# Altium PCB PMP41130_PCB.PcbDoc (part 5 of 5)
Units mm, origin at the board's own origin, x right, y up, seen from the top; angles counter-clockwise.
Board outline 74.13 x 200.91 mm, 6 copper layers (Top Layer, Layer 1, Inside Layer 1, Inside Layer 2, Layer 2, Bottom Layer), stack 2.208 mm thick; 356 components, 162 nets, 889 pads, 1511 vias.
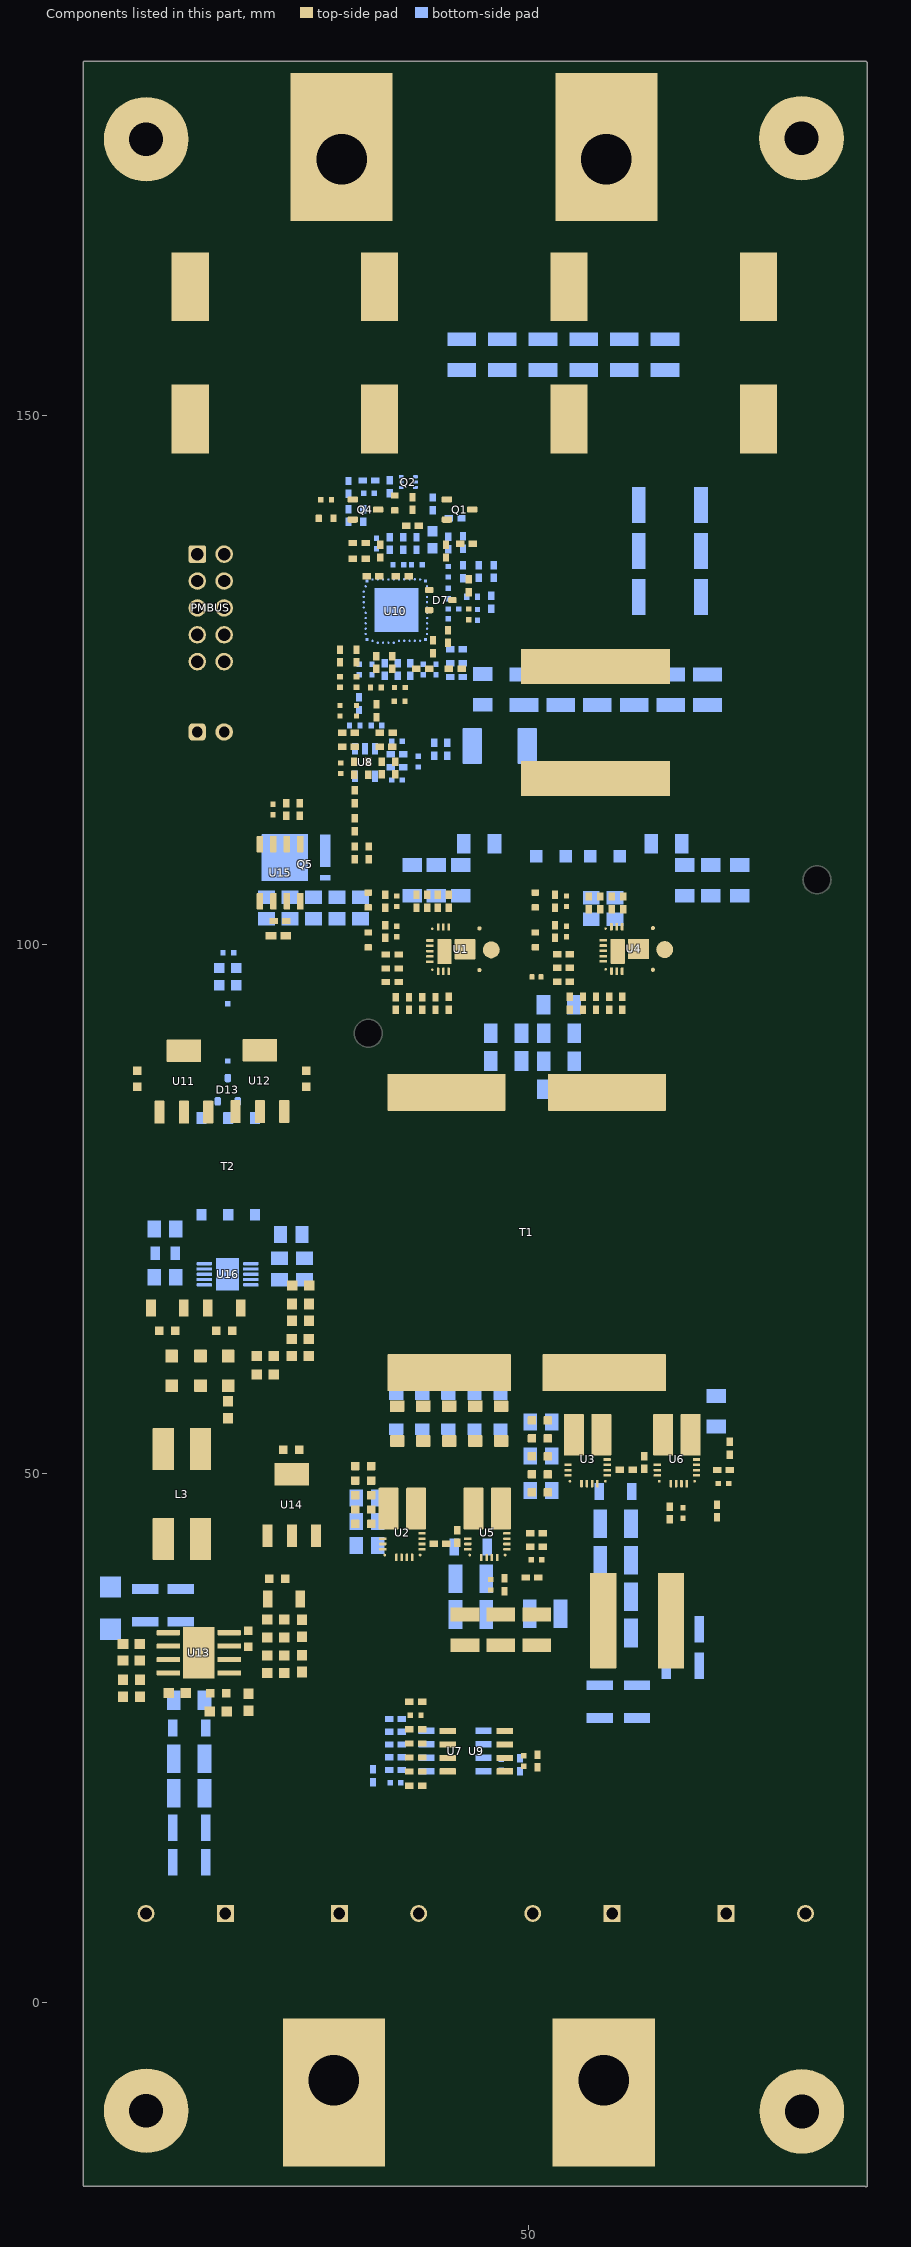
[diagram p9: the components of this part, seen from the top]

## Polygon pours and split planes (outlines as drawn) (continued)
SR_Source on Layer 2 "LAYER_2_SR_SOURCE_P201" (solid, remove dead copper, pour order 201): 43.648,112.63 46.238,115.219 46.238,120.747 38.988,120.747 38.988,114.483 36.03,114.483 36.03,112.125 38.988,109.168 38.988,98.9 39.846,98.042 63.538,98.042 64.269,98.773 64.269,101.19 43.648,101.19
SW3 on Layer 2 "LAYER_2_SW3_P186" (solid, remove dead copper, pour order 186): 59.882,95.876 59.882,90.943 59.154,90.215 55.037,90.215 55.037,84.24 63.665,84.24 63.665,95.876
SW4 on Layer 2 "LAYER_2_SW4_P183" (solid, remove dead copper, pour order 183): 43.459,95.876 43.459,91.061 43.026,90.628 38.212,90.628 37.348,89.764 37.348,84.266 47.828,84.266 47.828,95.876
GND on Layer 2 "LAYER_2_GND_P180" (solid, remove dead copper, pour order 180): 31.485,28.287 31.485,18.43 42.356,18.43 42.356,28.287
VOUT on Layer 2 "LAYER_2_VOUT_P153" (solid, remove dead copper, pour order 153): 62.459,127.394 52.655,127.394 52.655,146.557 51.72,147.492 8.046,147.492 8.046,154.902 68.533,154.902 68.533,144.5 68.268,144.234 62.459,144.234
AGND on Layer 2 "LAYER_2_AGND_P139" (solid, remove dead copper, pour order 139): 70.757,124.058 70.757,165.014 71.107,165.364 80.806,165.364 81.219,164.951 81.219,118.083 80.846,117.653 71.08,117.653 70.757,117.938
VIN_NEG on Layer 2 "LAYER_2_VIN_NEG_P103" (solid, remove dead copper, pour order 103): 32 vertices, not listed, extent 8.287,-15.551 81.124,10.431
VOUT on Layer 2 "LAYER_2_VOUT_P122" (solid, remove dead copper, pour order 122): 27.412,182.123 27.412,168.163 27.38,168.163 24.2,164.983 24.2,147.492 37.048,147.492 37.048,168.258 37.048,182.123
HS_Drain on Inside Layer 2 "INSIDE_LAYER_2_HS_DRAIN_P176" (solid, remove dead copper, pour order 176): 55.079,57.114 52.742,57.114 52.607,56.98 52.607,45.995 54.308,43.685 57.877,43.685 57.877,50.719 55.271,50.719 55.271,56.923
VIN_NEG on Inside Layer 2 "INSIDE_LAYER_2_VIN_NEG_P214" (solid, remove dead copper, pour order 214): 64.397,55.589 64.462,55.654 67.259,55.654 67.259,52.006 66.911,51.659 64.397,51.659
VIN_NEG on Inside Layer 2 "INSIDE_LAYER_2_VIN_NEG_P213" (solid, remove dead copper, pour order 213): 49.624,55.654 49.624,51.007 49.275,50.659 46.601,50.659 46.448,50.506 46.448,44.68 49.212,44.68 50.867,46.335 50.867,55.654
SR_Source on Inside Layer 2 "INSIDE_LAYER_2_SR_SOURCE_P210" (solid, remove dead copper, pour order 210): 38.988,100.766 38.988,98.9 39.624,98.264 45.889,98.264 63.761,98.264 64.269,98.773 64.269,100.766
SR_Source on Inside Layer 2 "INSIDE_LAYER_2_SR_SOURCE_P206" (solid, remove dead copper, pour order 206): 43.648,112.63 46.238,115.219 46.238,120.747 43.175,120.747 43.175,116.025 42.34,115.275 38.988,115.275 38.988,114.483 36.03,114.483 36.03,112.63
SR_Drain on Inside Layer 2 "INSIDE_LAYER_2_SR_DRAIN_P203" (solid, remove dead copper, pour order 203): 46.021,102.508 46.021,110.944 49.166,114.089 64.269,114.089 64.269,102.508 59.913,102.508 59.913,107.899 57.813,109.999 49.897,109.999 47.828,107.587 47.828,102.508
HS_Drain on Inside Layer 2 "INSIDE_LAYER_2_HS_DRAIN_P174" (solid, remove dead copper, pour order 174): 37.728,49.132 34.885,49.132 34.885,33.719 36.581,32.023 41.786,32.023 41.786,43.845 37.728,43.845
NetC1_2 on Inside Layer 2 "INSIDE_LAYER_2_NETC1_2_P195" (solid, remove dead copper, pour order 195): 36.889,57.736 36.889,62.427 48.348,62.427 48.348,57.736
SR_Drain on Inside Layer 2 "INSIDE_LAYER_2_SR_DRAIN_P134" (solid, remove dead copper, pour order 134): 47.828,108.659 34.377,108.659 34.377,110.969 46.07,110.969 47.828,112.728
SW3 on Inside Layer 2 "INSIDE_LAYER_2_SW3_P185" (solid, remove dead copper, pour order 185): 59.882,95.876 59.882,90.943 59.154,90.215 55.037,90.215 55.037,84.248 63.665,84.248 63.665,95.876
SW4 on Inside Layer 2 "INSIDE_LAYER_2_SW4_P182" (solid, remove dead copper, pour order 182): 43.459,95.876 43.459,91.061 43.026,90.628 39.022,90.628 37.895,89.501 37.895,84.269 47.828,84.269 47.828,95.876
HS_Drain on Inside Layer 2 "INSIDE_LAYER_2_HS_DRAIN_P175" (solid, remove dead copper, pour order 175): 54.31,46.175 57.877,46.175 57.877,32.023 39.512,32.023 39.512,35.013 54.31,35.013
VIN_NEG on Inside Layer 2 "INSIDE_LAYER_2_VIN_NEG_P173" (solid, remove dead copper, pour order 173): 16.09,26.584 8.682,26.584 8.682,1.622 8.936,1.367 15.646,1.367 16.09,1.811
SW2 on Inside Layer 2 "INSIDE_LAYER_2_SW2_P170" (solid, remove dead copper, pour order 170): 51.436,57.736 51.363,57.809 51.363,62.427 64.945,62.427 65.128,62.22 65.128,57.929 64.948,57.736 63.873,57.736 63.683,57.545 63.683,51.644 55.938,51.644 55.938,57.528 55.729,57.736
SW1 on Inside Layer 2 "INSIDE_LAYER_2_SW1_P169" (solid, remove dead copper, pour order 169): 36.996,51.931 36.889,52.038 36.889,54.005 36.977,54.093 48.242,54.093 48.348,53.986 48.348,52.056 48.223,51.931 46.019,51.931 45.784,51.696 45.784,44.712 38.442,44.712 38.442,51.931
VOUT on Inside Layer 2 "INSIDE_LAYER_2_VOUT_P161" (solid, remove dead copper, pour order 161): 62.665,127.394 52.623,127.394 52.623,146.557 51.688,147.492 8.014,147.492 8.014,154.902 68.502,154.902 68.502,144.5 68.236,144.234 62.665,144.234
VIN_POS on Inside Layer 2 "INSIDE_LAYER_2_VIN_POS_P148" (solid, remove dead copper, pour order 148): 20 vertices, not listed, extent 20.48,-15.837 69.596,15.01
VIN_NEG on Inside Layer 2 "INSIDE_LAYER_2_VIN_NEG_P145" (solid, remove dead copper, pour order 145): 23 vertices, not listed, extent 38.686,-15.551 81.124,55.705
AGND on Inside Layer 2 "INSIDE_LAYER_2_AGND_P138" (solid, remove dead copper, pour order 138): 70.789,124.026 70.789,164.983 71.138,165.332 80.838,165.332 81.251,164.919 81.251,118.051 80.877,117.621 71.112,117.621 70.789,117.906
VOUT on Inside Layer 2 "INSIDE_LAYER_2_VOUT_P124" (solid, remove dead copper, pour order 124): 27.412,182.123 27.412,168.163 27.38,168.163 24.2,164.983 24.2,147.683 37.048,147.683 37.048,168.258 37.048,182.123

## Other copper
Top Layer:
  pour cut-out: 44.203,127.012 44.203,126.567 44.108,126.472 41.595,126.472 41.595,127.012
  pour cut-out: 17.363,34.663 14.883,34.663 14.851,34.695 14.851,35.649 8.586,35.649 8.586,32.653 17.363,32.695
Inside Layer 1:
  pour cut-out: 41.564,32.259 34.772,32.259 34.772,39.102 41.564,39.102
  pour cut-out: 36.879,111.023 36.879,108.102 33.718,108.102 33.718,111.023
  pour cut-out: 60.056,101.346 63.173,101.346 63.173,104.014 60.056,104.014
  pour cut-out: 45.336,101.35 48.453,101.35 48.453,104.018 45.336,104.018
  pour cut-out: 59.021,96.462 59.021,93.345 64.777,93.345 64.777,96.462
  pour cut-out: 42.565,96.452 42.565,93.335 48.321,93.335 48.321,96.452
  pour cut-out: 58.1,34.842 58.1,31.61 48.623,31.61 48.46,31.773 48.46,34.716 48.586,34.842
  pour cut-out: 23.437,98.614 23.437,95.053 19.536,95.053 19.464,95.125 19.464,98.52 19.558,98.614
  pour cut-out: 61.662,24.646 61.662,28.207 68.308,28.207 68.308,24.646
  pour cut-out: 55.272,47.065 57.846,47.065 58.1,46.811 58.1,33.37 57.832,33.103 55.738,33.103 55.206,33.634 55.206,47
  pour cut-out: 68.308,24.646 65.108,24.646 65.108,37.43 68.308,37.43
  pour cut-out: 30.974,28.207 30.433,27.667 30.433,19.112 44.235,19.112 44.235,27.667 43.694,28.207
Layer 1:
  pour cut-out: 63.912,56.028 52.785,56.028 52.726,55.969 52.726,54.475 52.954,54.246 63.964,54.246 64.164,54.473 64.164,55.777
  pour cut-out: 46.423,52.899 37.793,52.899 37.698,52.805 37.698,50.662 37.891,50.469 46.369,50.469 46.532,50.653 46.532,52.79
  pour cut-out: 68.308,24.646 65.108,24.646 65.108,37.43 68.308,37.43
  pour cut-out: 61.662,24.646 61.662,28.207 68.308,28.207 68.308,24.646
  pour cut-out: 63.912,51.278 52.785,51.278 52.726,51.337 52.726,52.832 52.928,53.034 63.818,53.034 64.164,52.642 64.164,51.53
  pour cut-out: 45.994,44.295 35.716,44.295 35.387,44.624 35.387,45.706 35.749,46.067 45.885,46.067 46.245,45.659 46.245,44.546
  pour cut-out: 45.994,49.045 35.716,49.045 35.387,48.716 35.387,47.634 35.718,47.304 45.912,47.304 46.245,47.682 46.245,48.794
  pour cut-out: 58.1,34.874 58.1,31.642 48.623,31.642 48.46,31.805 48.46,34.747 48.586,34.874
  pour cut-out: 41.564,32.259 34.772,32.259 34.772,39.102 41.564,39.102
  pour cut-out: 23.501,98.646 23.501,95.085 19.6,95.085 19.528,95.156 19.528,98.552 19.622,98.646
  pour cut-out: 37.459,111.047 37.459,108.374 32.646,108.374 32.646,111.047
  pour cut-out: 55.27,47.097 57.75,47.097 58.1,46.747 58.1,33.37 57.832,33.103 55.738,33.103 55.27,33.57
Layer 2:
  pour cut-out: 41.564,32.259 34.772,32.259 34.772,39.102 41.564,39.102
  pour cut-out: 46.423,52.899 37.793,52.899 37.698,52.805 37.698,50.662 37.891,50.469 46.369,50.469 46.532,50.653 46.532,52.79
  pour cut-out: 45.994,49.045 35.716,49.045 35.387,48.716 35.387,47.634 35.713,47.309 45.916,47.309 46.245,47.682 46.245,48.794
  pour cut-out: 45.994,44.295 35.716,44.295 35.387,44.624 35.387,45.706 35.701,46.02 45.927,46.02 46.245,45.659 46.245,44.546
  pour cut-out: 64.164,56.161 52.726,56.161 52.726,54.475 52.932,54.268 63.814,54.268 64.164,54.665
  pour cut-out: 63.912,51.278 52.785,51.278 52.726,51.337 52.726,52.832 52.923,53.029 63.822,53.029 64.164,52.642 64.164,51.53
  pour cut-out: 68.308,24.646 65.108,24.646 65.108,37.43 68.308,37.43
  pour cut-out: 61.662,24.646 61.662,28.207 68.308,28.207 68.308,24.646
  pour cut-out: 58.1,34.842 58.1,31.433 48.46,31.433 48.46,34.716 48.586,34.842
  pour cut-out: 55.367,47.097 57.846,47.097 58.1,46.843 58.1,33.275 57.928,33.103 55.833,33.103 55.27,33.666 55.27,47
  pour cut-out: 19.271,112.734 31.992,112.734 31.992,94.226 19.271,94.226
Bottom Layer:
  pour cut-out: 51.199,45.984 51.263,46.048 52.958,46.048 53.035,45.971 53.035,38.034 52.376,38.034 52.376,34.622 51.199,34.622 51.199,38.034
  pour cut-out: 39.56,94.671 39.401,94.512 39.401,93.049 39.56,92.89 43.026,92.89 43.185,93.049 43.185,94.48 42.995,94.671
  pour cut-out: 56.065,94.703 55.906,94.544 55.906,93.081 56.065,92.922 59.531,92.922 59.69,93.081 59.69,94.512 59.499,94.703
  pour cut-out: 25.282,48.88 30.084,48.88 30.084,54.825 25.282,54.825

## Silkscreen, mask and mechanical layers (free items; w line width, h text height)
Top Overlay:
  text "PMP41130 HSFB" at 75.372,110.538 h2 r90
  text "Telecom Power Supply Unit" at 77.93,110.409 h1.5 r90
Top Paste:
  text ".Layer_Name" at 14.656,-21.806 h1.52
Bottom Paste:
  text ".Layer_Name" at 14.656,-21.806 h1.52
Top Solder:
  text ".Layer_Name" at 14.656,-21.806 h1.52
  text ".Layer_Name" at 14.656,-21.806 h1.52
Bottom Solder:
  text ".Layer_Name" at 14.656,-21.806 h1.52
Drill Guide:
  text ".Layer_Name" at 14.656,-21.806 h1.52
M1 Board Outline:
  lines w0.254: 8.046,-17.3 8.046,183.3 ; 8.046,183.325 81.855,183.325 ; 8.077,-17.303 81.887,-17.303 ; 81.919,-17.331 81.919,183.268
M2 Board Dimensions:
  rectangle: 0,-6.985 3.175,-3.81
  rectangle: 3.175,-10.16 12.7,-6.985
  lines w0.178: 0,-6.985 25.4,-6.985 ; 3.175,-10.16 3.175,-3.81 ; 6.35,-10.16 6.35,-3.81 ; 12.7,-10.16 12.7,-3.81 ; 19.05,-10.16 19.05,-3.81 ; 0,-10.16 25.4,-10.16 25.4,-3.81 0,-3.81 0,-10.16
  text ".Layer_Name" at 14.656,-21.806 h1.52
M3 3D STEP Top:
  text ".Layer_Name" at 14.656,-21.806 h1.52
M4 3D STEP Bottom:
  text ".Layer_Name" at 14.656,-21.806 h1.52
M5 Assembly Top:
  lines w0.254: -7.417,-23.626 160.223,-23.626 ; -7.417,-18.462 160.274,-18.462 ; -7.417,-13.297 -7.417,-28.791 94.31,-28.791 160.274,-28.791 160.274,-13.297 -7.404,-13.297 -7.404,-28.791 32.614,-28.791 ; 55.194,-28.791 55.194,-13.297 ; 87.376,-18.462 87.376,-13.297 ; 108.712,-18.462 108.712,-13.297 ; 124.511,-28.956 124.511,-23.804
  text "COMPONENTS MARKED 'DNP' SHOULD NOT BE POPULATED." at 29.299,-8.09 h1.52
  text "ASSEMBLY VARIANT:" at 29.286,-11.024 h1.52
  text ".VariantName" at 55.601,-11.024 h1.52
  text "PCB VIEWED FROM TOP SIDE" at -5.804,-16.654 h1.52
  text "BOARD #:" at 57.099,-16.654 h1.52
  text ".PRJ_Number" at 70.955,-16.654 h1.52
  text "REV:" at 92.405,-16.654 h1.52
  text ".PCB_Rev" at 99.809,-16.654 h1.52
  text "SVN REV:" at 113.69,-16.654 h1.52
  text ".VersionControl_RevNumber" at 126.543,-16.654 h1.52
  text "TID #:" at 57.099,-21.819 h1.52
  text ".TID" at 70.955,-21.819 h1.52
  text "PLOT NAME =" at -5.804,-27.034 h1.52
  text ".plot_File_Name" at 14.656,-27.034 h1.52
  text "GENERATED    :" at 57.15,-27.034 h1.52
  text ".Print_Date" at 79.235,-27.034 h1.52
  text ".Print_Time" at 97.752,-27.034 h1.52
  text "TEXAS INSTRUMENTS" at 129.87,-27.034 h1.52
M6 Assembly Bottom:
  lines w0.254: -7.429,-18.474 160.261,-18.474 ; -7.379,-23.639 160.261,-23.639 ; 28.334,-28.969 28.334,-23.817 ; 44.133,-18.474 44.133,-13.31 ; 65.468,-18.474 65.468,-13.31 ; 97.65,-28.804 97.65,-13.31 ; 120.231,-28.804 160.249,-28.804 160.249,-13.31 -7.429,-13.31 -7.429,-28.804 58.534,-28.804 160.261,-28.804 160.261,-13.31
  text "COMPONENTS MARKED 'DNP' SHOULD NOT BE POPULATED." at 154.991,-8.077 h1.52
  text ".VariantName" at 128.473,-11.024 h1.52
  text "ASSEMBLY VARIANT:" at 154.864,-11.024 h1.52
  text ".VersionControl_RevNumber" at 26.302,-16.667 h1.52
  text "SVN REV:" at 39.154,-16.667 h1.52
  text ".PCB_Rev" at 53.035,-16.667 h1.52
  text "REV:" at 60.439,-16.667 h1.52
  text ".PRJ_Number" at 81.89,-16.667 h1.52
  text "BOARD #:" at 95.745,-16.667 h1.52
  text "PCB VIEWED FROM BOTTOM SIDE" at 158.648,-16.667 h1.52
  text ".TID" at 81.89,-21.831 h1.52
  text "TID #:" at 95.745,-21.831 h1.52
  text "TEXAS INSTRUMENTS" at 22.974,-27.047 h1.52
  text ".Print_Time" at 55.093,-27.047 h1.52
  text ".Print_Date" at 73.609,-27.047 h1.52
  text "GENERATED    :" at 95.694,-27.047 h1.52
  text ".plot_File_Name" at 138.189,-27.047 h1.52
  text "PLOT NAME =" at 158.648,-27.047 h1.52
M9 Title Sheet:
  drawing of 57 lines, arcs and shapes, not listed
  text "1" at 18.792,204.127 h1.78
  text "2" at 82.182,204.127 h1.78
  text "3" at 145.411,204.127 h1.78
  text "4" at 209.08,204.127 h1.78
  text "5" at 272.555,204.127 h1.78
  text "6" at 336.182,204.127 h1.78
  text "A" at -10.579,175.095 h1.78
  text "A" at 365.341,175.095 h1.78
  text "B" at -10.579,114.643 h1.78
  text "B" at 365.341,114.643 h1.78
  text "C" at -10.579,54.318 h1.78
  text "C" at 365.341,54.318 h1.78
  text "PROJECT TITLE:" at 288.125,7.048 h1.14
  text ".PRJ_Title" at 289.395,3.662 h1.78
  text "DESIGNED FOR:" at 288.125,-0.597 h1.14
  text ".PRJ_Customer" at 289.395,-4.153 h1.78
  text "D" at -10.579,-5.88 h1.78
  text "D" at 365.341,-5.88 h1.78
  text "FILE NAME:" at 288.125,-8.217 h1.14
  text ".PCB_File_Name_No_Path" at 289.395,-11.265 h1.78
  text "Texas Instruments (TI) and/or its licensors do not warrant the accuracy or completeness of this specification" at 161.9,-15.376 h1.14
  text "ENGINEER:" at 288.125,-15.583 h1.14
  text "LAYOUT BY:" at 326.352,-15.583 h1.14
  text "or any information contained therein. TI and/or its licensors do not warrant that this design will meet" at 160.757,-18.237 h1.14
  text ".PRJ_Engineer" at 289.395,-19.52 h1.78
  text ".PCB_Layout" at 327.635,-19.52 h1.78
  text "the specifications, will be suitable for your application or fit for any particular purpose, or will operate in" at 160.757,-21.099 h1.14
  text ".Layer_Name" at 14.656,-21.806 h1.52
  text "ALTIUM DESIGNER VERSION:" at 326.352,-23.457 h1.14
  text "an implementation. TI and/or its licensors do not warrant that the design is production worthy. You should" at 160.757,-23.961 h1.14
  text "completely validate and test your design implementation to confirm the system functionality for your application." at 161.9,-26.822 h1.14
  text ".print_Scale" at 289.395,-26.843 h1.78
  text ".Application_BuildNumber" at 327.635,-26.843 h1.78
  text "1" at 18.792,-32.093 h1.78
  text "2" at 82.182,-32.093 h1.78
  text "3" at 145.411,-32.093 h1.78
  text "4" at 209.08,-32.093 h1.78
  text "5" at 272.555,-32.093 h1.78
  text "6" at 336.182,-32.093 h1.78
M10 Fab Notes:
  drawing of 189 lines, arcs and shapes, not listed
  text "DESIGN INFORMATION" at 314.503,161.447 h1.52
  text "MIN. TRACK WIDTH:" at 298.131,158.091 h1.52
  text "8" at 325.976,158.091 h1.52
  text "MIL" at 329.907,158.091 h1.52
  text "7.874" at 321.75,155 h1.52
  text "MIN. CLEARANCE:" at 298.131,154.938 h1.52
  text "MIL" at 329.907,154.938 h1.52
  text "MIN. VIA PAD SIZE:" at 298.131,151.785 h1.52
  text "24" at 325.214,151.785 h1.52
  text "MIL" at 329.907,151.785 h1.52
  text "0.05mm (2MIL)" at 315.784,148.486 h1.52
  text "MINIMUM ANNULAR RING" at 289.769,148.277 h1.52
  text "EXTERNAL" at 333.768,148.277 h1.52
  text "PER" at 294.849,145.48 h1.52
  text "IPC-D-275 CLASS 2 LEVEL C" at 300.437,145.48 h1.52
  text "MIL, HOLES" at 338.238,142.928 h1.52
  text "+/-" at 328.27,142.709 h1.52
  text "+/-" at 349.961,142.709 h1.52
  text "REGISTRATION TOLERANCES:" at 289.769,142.682 h1.52
  text "METAL" at 320.243,142.682 h1.52
  text "5" at 334.879,142.683 h1.52
  text "3" at 356.037,142.683 h1.52
  text "MIL" at 358.99,142.682 h1.52
  text "HOLE SIZE TOLERANCE (UNLESS OTHERWISE SPECIFIED):" at 289.769,140.185 h1.52
  text "+/-" at 349.961,140.112 h1.52
  text "3" at 356.037,140.085 h1.52
  text "MIL" at 358.99,140.085 h1.52
  text "MATERIAL:" at 287.87,136.589 h1.52
  text "FR-4 High Tg" at 312.926,133.324 h1.52
  text "X" at 309.257,133.122 h1.52
  text "FR-4" at 298.563,133.007 h1.52
  text "OTHER" at 336.358,133.007 h1.52
  text "62 MIL (1.6mm) +/-10%" at 306.694,129.374 h1.52
  text "X" at 303.643,129.312 h1.52
  text "THICKNESS:" at 289.769,129.165 h1.52
  text "OTHER" at 339.33,129.165 h1.52
  text "TOLERANCE:" at 289.769,125.652 h1.52
  text "X" at 311.314,125.652 h1.52
  text "ANSI IPC-6012 TYPE 3 CLASS 2" at 315.836,125.652 h1.52
  text "OTHER +/-" at 315.835,121.989 h1.52
  text "BOW & TWIST:" at 289.769,118.302 h1.52
  text "X" at 311.314,118.302 h1.52
  text "ANSI IPC-6012 TYPE 3 CLASS 2" at 315.836,118.302 h1.52
  text "OTHER +/-" at 315.835,114.576 h1.52
  text "DRILLING:" at 287.87,111.258 h1.52
  text "NC_DRILL FILES" at 332.599,108.586 h1.52
  text "REFERENCE:" at 289.769,108.486 h1.52
  text "X" at 306.463,108.484 h1.52
  text "AS SHOWN" at 310.984,108.486 h1.52
  text "X" at 329.348,108.486 h1.52
  text "OTHER" at 340.168,104.873 h1.52
  text "PTH COPPER THICKNESS:" at 289.761,104.783 h1.52
  text "X" at 318.697,104.783 h1.52
  text "20-30 um" at 321.948,104.783 h1.52
  text "BOARD FINISH:" at 287.87,101.034 h1.52
  text "SILKSCREEN:" at 291.812,98.237 h1.52
  text "X" at 316.14,98.237 h1.52
  text "TOP" at 319.112,98.237 h1.52
  text "X" at 329.094,98.237 h1.52
  text "BOTTOM" at 332.091,98.237 h1.52
  text "SILKSCREEN COLOR:" at 291.812,94.295 h1.52
  text "X" at 316.115,94.295 h1.52
  text "WHITE" at 319.112,94.295 h1.52
  text "OTHER" at 332.091,94.295 h1.52
  text "X" at 319.442,90.652 h1.52
  text "GREEN" at 322.439,90.652 h1.52
  text "OTHER" at 338.136,90.652 h1.52
  text "SOLDER RESIST COLOR:" at 291.812,90.477 h1.52
  text "X" at 319.442,86.734 h1.52
  text "MATTE" at 322.439,86.734 h1.52
  text "SEMI-GLOSS" at 338.125,86.717 h1.52
  text "IMMERSION GOLD (ENIG)" at 314.819,82.345 h1.52
  text "ENEPIG" at 348.793,82.162 h1.52
  text "SURFACE FINISH:" at 287.87,82.136 h1.52
  text "X" at 310.298,82.136 h1.52
  text "IMM. TIN/SILVER OR EQUIV" at 296.24,78.649 h1.52
  text "OTHER" at 332.599,78.549 h1.52
  text "ARRAY/PANEL:" at 287.87,74.602 h1.52
  text "CUT AND TRIM PER M1 BOARD OUTLINE" at 314.819,74.393 h1.52
  text "N.C. ROUTE" at 314.819,70.94 h1.52
  text "X" at 332.295,70.94 h1.52
  text "V. SCORE" at 336.816,70.94 h1.52
  text "CERTIFICATION:" at 287.87,67.66 h1.52
  text "MATERIALS AND WORKMANSHIP FOR ALL PCBS" at 306.285,67.66 h1.52
  text "TO MEET OR EXCEED THE REQUIREMENTS OF:" at 306.285,65.271 h1.52
  text "X" at 297.078,62.003 h1.52
  text "ANSI IPC-A-600F CLASS ->" at 300.329,62.003 h1.52
  text "X" at 342.188,62.003 h1.52
  text "2" at 344.982,62.003 h1.52
  text "1" at 336.981,61.965 h1.52
  text "3" at 353.973,61.965 h1.52
  text "X" at 317.702,58.252 h1.52
  text "RoHS" at 320.953,58.252 h1.52
  text "OTHER" at 337.321,58.252 h1.52
  text "PER ORDER" at 347.407,58.252 h1.52
  text "ALL BOARDS MUST MEET OR EXCEED UL94-V0 REQUIREMENTS." at 288.569,54.345 h1.52
  text "PCB MUST BEAR THE UL94V-0 UL REGISTERED MATERIAL ID NUMBER" at 288.569,51.397 h1.52
  text "ADDITIONAL REQUIREMENTS:" at 287.87,47.094 h1.52
  text "MICROSECTION:" at 289.769,44.373 h1.52
  text "YES" at 312.775,44.373 h1.52
  text "REQUIRED" at 334.657,40.707 h1.52
  text "BARE BOARD ELEC. TEST:" at 289.769,40.634 h1.52
  text "NONE" at 322.935,40.634 h1.52
  text "X" at 331.66,40.634 h1.52
  text "PER ORDER" at 349.693,40.634 h1.52
  text "XX MIL VIAS REQUIRE NON-CONDUCTIVE FILL AND PLANARIZE" at 294.04,35.428 h1.5
  text "XX MIL VIAS REQUIRE CONDUCTIVE FILL AND PLANARIZE" at 294.243,32.787 h1.52
  text "OUTER XX MIL TRACES REQUIRE 50 OHM SINGLE-ENDED IMPEDANCE" at 294.218,28.637 h1.47
  text "LAYER 2 & 3 (INNER LAYERS) XX MIL WIDE, XX MIL SPACE / TRACES REQUIRE 100 OHM DIFFERENTIAL IMPEDANCE" at 294.015,22.65 h1.52
  text ".Layer_Name" at 14.656,-21.806 h1.52
M11 Gerber Information:
  lines w0.254: -7.417,-23.626 160.223,-23.626 ; -7.417,-18.462 160.274,-18.462 ; -7.417,-13.297 -7.417,-28.791 94.31,-28.791 160.274,-28.791 160.274,-13.297 -7.404,-13.297 -7.404,-28.791 32.614,-28.791 ; 55.194,-28.791 55.194,-13.297 ; 87.376,-18.462 87.376,-13.297 ; 108.712,-18.462 108.712,-13.297 ; 124.511,-28.956 124.511,-23.804
  text "ALL ARTWORK VIEWED FROM TOP SIDE" at -5.804,-16.654 h1.52
  text "BOARD #:" at 57.099,-16.654 h1.52
  text ".PRJ_Number" at 70.955,-16.654 h1.52
  text "REV:" at 92.405,-16.654 h1.52
  text ".PCB_Rev" at 99.809,-16.654 h1.52
  text "SVN REV:" at 113.69,-16.654 h1.52
  text ".VersionControl_RevNumber" at 126.543,-16.654 h1.52
  text "LAYER NAME =" at -5.804,-21.806 h1.52
  text "TID #:" at 57.099,-21.819 h1.52
  text ".TID" at 70.955,-21.819 h1.52
  text "PLOT NAME =" at -5.804,-27.034 h1.52
  text ".plot_File_Name" at 14.656,-27.034 h1.52
  text "GENERATED    :" at 57.15,-27.034 h1.52
  text ".Print_Date" at 79.235,-27.034 h1.52
  text ".Print_Time" at 97.752,-27.034 h1.52
  text "TEXAS INSTRUMENTS" at 129.87,-27.034 h1.52
M12 Stackup:
  drawing of 399 lines, arcs and shapes, not listed
  text "Layer" at 249.469,200.023 h1.52
  text "Name" at 259.88,200.023 h1.52
  text "Material" at 283.75,200.023 h1.52
  text "Thickness" at 305.588,200.023 h1.52
  text "Constant" at 322.094,200.023 h1.52
  text "Board Layer Stack" at 336.568,200.023 h1.52
  text "Top Overlay" at 259.88,196.975 h1.52
  text "Top Solder" at 259.88,193.927 h1.52
  text "Solder Resist" at 283.75,193.927 h1.52
  text "0.40mil" at 305.588,193.927 h1.52
  text "3.5" at 322.094,193.927 h1.52
  text "1" at 249.469,190.879 h1.52
  text "Top Layer" at 259.88,190.879 h1.52
  text "2.76mil" at 305.588,190.879 h1.52
  text "Dielectric 3" at 259.88,187.831 h1.52
  text "PP-006" at 283.75,187.831 h1.52
  text "2.80mil" at 305.588,187.831 h1.52
  text "4.1" at 322.094,187.831 h1.52
  text "2" at 249.469,184.783 h1.52
  text "Layer 1" at 259.88,184.783 h1.52
  text "CF-004" at 283.75,184.783 h1.52
  text "2.76mil" at 305.588,184.783 h1.52
  text "Dielectric 1" at 259.88,181.735 h1.52
  text "PP-006" at 283.75,181.735 h1.52
  text "2.80mil" at 305.588,181.735 h1.52
  text "4.1" at 322.094,181.735 h1.52
  text "3" at 249.469,178.687 h1.52
  text "Inside Layer 1" at 259.88,178.687 h1.52
  text "CF-004" at 283.75,178.687 h1.52
  text "2.76mil" at 305.588,178.687 h1.52
  text "Dielectric1" at 259.88,175.639 h1.52
  text "FR-4 High Tg" at 283.75,175.639 h1.52
  text "59.20mil" at 305.588,175.639 h1.52
  text "4.8" at 322.094,175.639 h1.52
  text "4" at 249.469,172.591 h1.52
  text "Inside Layer 2" at 259.88,172.591 h1.52
  text "CF-004" at 283.75,172.591 h1.52
  text "2.76mil" at 305.588,172.591 h1.52
  text "Dielectric 2" at 259.88,169.543 h1.52
  text "PP-006" at 283.75,169.543 h1.52
  text "2.80mil" at 305.588,169.543 h1.52
  text "4.1" at 322.094,169.543 h1.52
  text "5" at 249.469,166.495 h1.52
  text "Layer 2" at 259.88,166.495 h1.52
  text "CF-004" at 283.75,166.495 h1.52
  text "2.76mil" at 305.588,166.495 h1.52
  text "Dielectric 4" at 259.88,163.447 h1.52
  text "PP-006" at 283.75,163.447 h1.52
  text "2.80mil" at 305.588,163.447 h1.52
  text "4.1" at 322.094,163.447 h1.52
  text "6" at 249.469,160.399 h1.52
  text "Bottom Layer" at 259.88,160.399 h1.52
  text "2.76mil" at 305.588,160.399 h1.52
  text "Bottom Solder" at 259.88,157.351 h1.52
  text "Solder Resist" at 283.75,157.351 h1.52
  text "0.40mil" at 305.588,157.351 h1.52
  text "3.5" at 322.094,157.351 h1.52
  text "Bottom Overlay" at 259.88,154.303 h1.52
  text ".Layer_Name" at 14.656,-21.806 h1.52
M13 Component Bodies Top:
  text ".Layer_Name" at 14.656,-21.806 h1.52
M14 Component Bodies Bottom:
  text ".Layer_Name" at 14.656,-21.806 h1.52
M15 Courtyards Top:
  text ".Layer_Name" at 14.656,-21.806 h1.52
M16 Courtyards Bottom:
  text ".Layer_Name" at 14.656,-21.806 h1.52
Drill Drawing:
  circle w0.254: c136.238,61.469 r0.421
  circle w0.254: c136.238,61.469 r0.702
  circle w0.254: c136.238,55.154 r0.702
  lines w0.254: 135.537,51.645 135.888,51.645 136.238,51.294 136.589,51.645 136.94,51.645 136.589,51.996 136.94,52.347 136.589,52.347 136.238,52.698 135.888,52.347 135.537,52.347 135.888,51.996 135.537,51.645 ; 135.537,57.61 136.94,57.61 136.94,59.013 135.537,59.013 135.537,57.61 ; 135.537,64.627 136.238,63.925 136.94,64.627 136.238,65.329 135.537,64.627 ; 135.537,67.083 135.537,67.434 135.888,67.785 135.537,68.135 135.537,68.486 135.888,68.486 136.238,68.135 136.589,68.486 136.94,68.486 136.94,68.135 136.589,67.785 136.94,67.434 136.94,67.083 136.589,67.083 136.238,67.434 135.888,67.083 135.537,67.083 ; 135.537,71.644 136.94,71.644 136.238,70.241 135.537,71.644 ; 135.537,73.749 135.888,73.749 135.888,73.398 136.589,73.398 136.589,73.749 136.94,73.749 136.94,74.451 136.589,74.451 136.589,74.802 135.888,74.802 135.888,74.451 135.537,74.451 135.537,73.749 ; 135.537,76.556 136.94,76.556 136.94,77.959 135.537,77.959 135.537,76.556 ; 135.537,79.714 136.238,80.065 136.94,79.714 136.589,80.415 136.94,81.117 136.238,80.766 135.537,81.117 135.888,80.415 135.537,79.714 ; 135.537,83.222 135.888,83.222 136.238,82.871 136.589,83.222 136.94,83.222 136.589,83.573 136.94,83.924 136.589,83.924 136.238,84.275 135.888,83.924 135.537,83.924 135.888,83.573 135.537,83.222 ; 135.817,51.785 136.028,51.785 136.238,51.575 136.449,51.785 136.659,51.785 136.449,51.996 136.659,52.206 136.449,52.206 136.238,52.417 136.028,52.206 135.817,52.206 136.028,51.996 135.817,51.785 ; 135.817,71.363 136.659,71.363 136.238,70.521 135.817,71.363 ; 135.817,76.837 136.659,76.837 136.659,77.679 135.817,77.679 135.817,76.837
  lines w0.305: 134.264,50.347 216.344,50.347 ; 134.264,85.082 216.344,85.082 ; 142.846,47.189 142.846,88.24 ; 151.279,47.189 151.279,88.24 ; 167.448,47.189 167.448,88.24 ; 174.03,47.189 174.03,88.24 ; 183.559,47.189 183.559,88.24 ; 201.957,47.189 201.957,88.24 ; 134.264,47.189 216.344,47.189 216.344,88.24 134.264,88.24 134.264,47.189
  text "Symbol" at 136.159,86.029 h1.83
  text "Quantity" at 143.793,86.029 h1.83
  text "Finished Hole Size" at 152.226,86.029 h1.83
  text "Plated" at 168.395,86.029 h1.83
  text "Hole Type" at 174.977,86.029 h1.83
  text "Drill Layer Pair" at 184.506,86.029 h1.83
  text "Hole Tolerance" at 202.904,86.029 h1.83
  text "28" at 143.793,82.871 h1.52
  text "7.87mil (0.200mm)" at 152.226,82.871 h1.52
  text "PTH" at 168.395,82.871 h1.52
  text "Round" at 174.977,82.871 h1.52
  text "Top Layer - Bottom Layer" at 184.506,82.871 h1.52
  text "310" at 143.793,79.714 h1.52
  text "8.00mil (0.203mm)" at 152.226,79.714 h1.52
  text "PTH" at 168.395,79.714 h1.52
  text "Round" at 174.977,79.714 h1.52
  text "Top Layer - Bottom Layer" at 184.506,79.714 h1.52
  text "1051" at 143.793,76.556 h1.52
  text "12.00mil (0.305mm)" at 152.226,76.556 h1.52
  text "PTH" at 168.395,76.556 h1.52
  text "Round" at 174.977,76.556 h1.52
  text "Top Layer - Bottom Layer" at 184.506,76.556 h1.52
  text "6" at 143.793,73.398 h1.52
  text "12.99mil (0.330mm)" at 152.226,73.398 h1.52
  text "PTH" at 168.395,73.398 h1.52
  text "Round" at 174.977,73.398 h1.52
  text "Top Layer - Bottom Layer" at 184.506,73.398 h1.52
  text "112" at 143.793,70.241 h1.52
  text "16.00mil (0.406mm)" at 152.226,70.241 h1.52
  text "PTH" at 168.395,70.241 h1.52
  text "Round" at 174.977,70.241 h1.52
  text "Top Layer - Bottom Layer" at 184.506,70.241 h1.52
  text "2" at 143.793,67.083 h1.52
  text "40.00mil (1.016mm)" at 152.226,67.083 h1.52
  text "PTH" at 168.395,67.083 h1.52
  text "Round" at 174.977,67.083 h1.52
  text "Top Layer - Bottom Layer" at 184.506,67.083 h1.52
  text "8" at 143.793,63.925 h1.52
  text "43.31mil (1.100mm)" at 152.226,63.925 h1.52
  text "PTH" at 168.395,63.925 h1.52
  text "Round" at 174.977,63.925 h1.52
  text "Top Layer - Bottom Layer" at 184.506,63.925 h1.52
  text "10" at 143.793,60.767 h1.52
  text "45.28mil (1.150mm)" at 152.226,60.767 h1.52
  text "PTH" at 168.395,60.767 h1.52
  text "Round" at 174.977,60.767 h1.52
  text "Top Layer - Bottom Layer" at 184.506,60.767 h1.52
  text "2" at 143.793,57.61 h1.52
  text "98.43mil (2.500mm)" at 152.226,57.61 h1.52
  text "PTH" at 168.395,57.61 h1.52
  text "Round" at 174.977,57.61 h1.52
  text "Top Layer - Bottom Layer" at 184.506,57.61 h1.52
  text "4" at 143.793,54.452 h1.52
  text "125.98mil (3.200mm)" at 152.226,54.452 h1.52
  text "PTH" at 168.395,54.452 h1.52
  text "Round" at 174.977,54.452 h1.52
  text "Top Layer - Bottom Layer" at 184.506,54.452 h1.52
  text "4" at 143.793,51.294 h1.52
  text "188.00mil (4.775mm)" at 152.226,51.294 h1.52
  text "PTH" at 168.395,51.294 h1.52
  text "Round" at 174.977,51.294 h1.52
  text "Top Layer - Bottom Layer" at 184.506,51.294 h1.52
  text "1537 Total" at 143.793,48.136 h1.52
  text ".Layer_Name" at 14.656,-21.806 h1.52
M17 Embedded Cavity:
  text ".Layer_Name" at 14.656,-21.806 h1.52
M18 Embedded Assembly:
  text ".Layer_Name" at 14.656,-21.806 h1.52
M19 Embedded Keepout:
  text ".Layer_Name" at 14.656,-21.806 h1.52

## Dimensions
0,-10.16 to 25.4,-10.16 on M2 Board Dimensions
0,0 to 8.046,183.453 on M2 Board Dimensions
0,0 to 7.918,183.3 on M2 Board Dimensions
